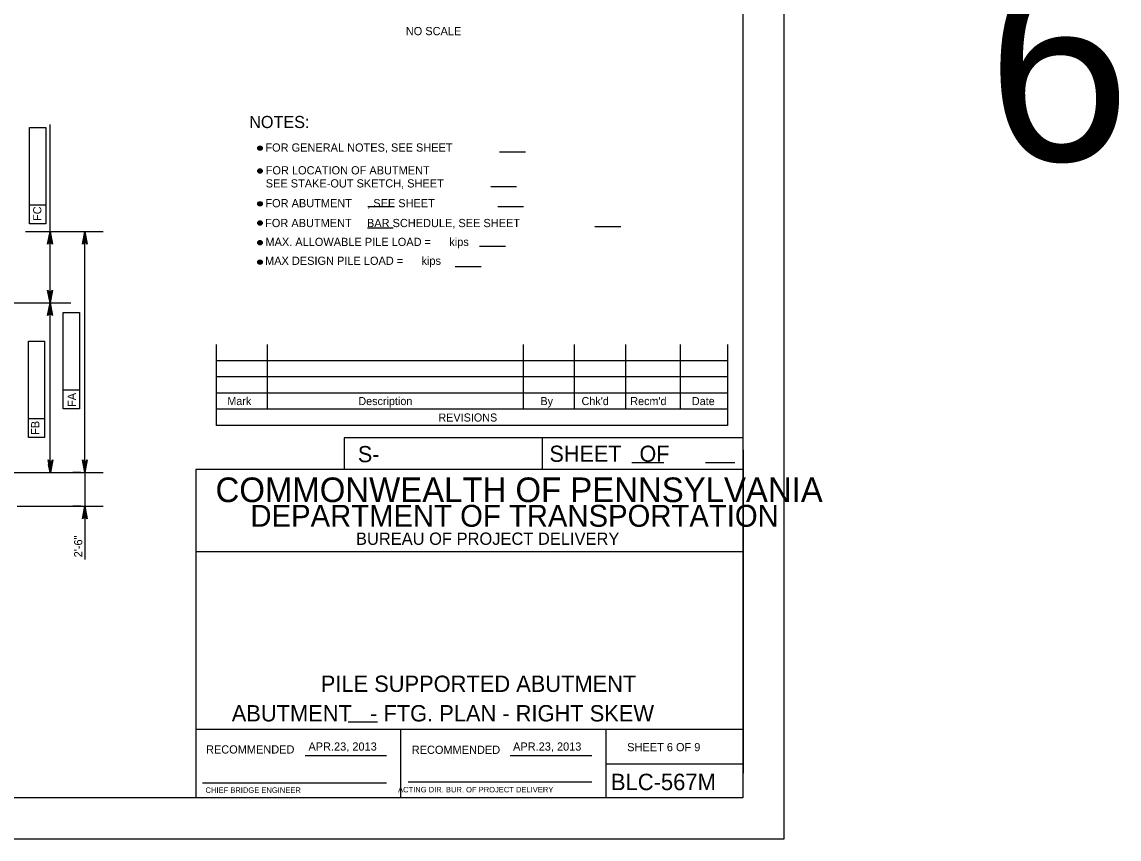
# Model space of a CAD drawing. Extents: x 638340 to 640242, y 295465 to 298435.
# Drawn here: x 639838.9 to 640240, y 297841.5 to 298140 of the extents above; entities that cross this region are included whole.
import ezdxf

# ---------------------------------------------------------------- set-up
doc = ezdxf.new("R2010")
doc.units = 0
for name, color, linetype in [('1', 7, 'Continuous'), ('2', 7, 'Continuous'), ('3', 7, 'Continuous'), ('4', 7, 'Continuous'), ('53', 7, 'Continuous'), ('Level 3', 7, 'Continuous'), ('Level 4', 7, 'Continuous'), ('PLT-BNDY', 7, 'Continuous')]:
    doc.layers.add(name, color=color, linetype=linetype)

msp = doc.modelspace()

# ---------------------------------------------------------------- linework, layer by layer
at = {"layer": '2'}
for p, q in [((640102.46, 298420.46), (640102.46, 297856.46)), ((639909.92, 298022.15), (639909.92, 297992.62)), ((639928.62, 298022.15), (639928.62, 297998.53)), ((640022.13, 298022.15), (640022.13, 297998.53)), ((640040.83, 298022.15), (640040.83, 297998.53)), ((640059.53, 298022.15), (640059.53, 297998.53)), ((640079.59, 298022.15), (640079.59, 297998.53)), ((640096.94, 298022.15), (640096.94, 297992.62)), ((640096.94, 298016.24), (639909.92, 298016.24)), ((640096.94, 298010.34), (639909.92, 298010.34)), ((640096.94, 298004.43), (639909.92, 298004.43)), ((640096.94, 297998.53), (639909.92, 297998.53)), ((640096.94, 297992.62), (639909.92, 297992.62)), ((640102.46, 297988.11), (639956.78, 297988.11)), ((639956.78, 297988.11), (639956.78, 297976.46)), ((640029.09, 297988.11), (640029.09, 297976.46)), ((640102.46, 297988.11), (640102.46, 297976.46)), ((640102.69, 297865.55), (640102.69, 297983.66)), ((640061.95, 297979), (640073.6, 297979)), ((640088.83, 297979), (640099.56, 297979)), ((640102.46, 297976.46), (639902.46, 297976.46)), ((639902.46, 297976.46), (639902.46, 297856.46)), ((640102.46, 297946.46), (639902.46, 297946.46)), ((640102.46, 297881.46), (639902.46, 297881.46)), ((639977.46, 297856.46), (639977.46, 297881.46)), ((640052.46, 297881.46), (640052.46, 297856.46)), ((639942.42, 297871.96), (639972.19, 297871.96)), ((640017.42, 297871.96), (640047.33, 297871.96)), ((640052.46, 297868.96), (640102.46, 297868.96)), ((639904.96, 297861.96), (639972.19, 297861.96)), ((639980.08, 297862.33), (640047.33, 297862.33)), ((640102.46, 297856.46), (639316.46, 297856.46))]:
    msp.add_line(p, q, dxfattribs=at)
at = {"layer": '4'}
msp.add_line((639958.24, 297884.3), (639968.9, 297884.3), dxfattribs=at)
at = {"layer": 'Level 3'}
for p, q in [((640013.58, 298092.62), (640023.03, 298092.62)), ((640010.33, 298079.91), (640019.78, 298079.91)), ((639965.42, 298072.63), (639974.86, 298072.63)), ((640012.91, 298072.62), (640022.35, 298072.62)), ((640048.43, 298065.3), (640057.88, 298065.3)), ((639965.22, 298064.83), (639974.66, 298064.83)), ((640006.25, 298058.17), (640015.7, 298058.17)), ((639997.35, 298050.73), (640006.8, 298050.73))]:
    msp.add_line(p, q, dxfattribs=at)
for centre, radius in [((639925.96, 298093.93), 0.832), ((639925.96, 298093.93), 0.624), ((639925.96, 298093.93), 0.416), ((639925.96, 298093.93), 0.208), ((639925.96, 298085.57), 0.832), ((639925.96, 298085.57), 0.624), ((639925.96, 298085.57), 0.416), ((639925.96, 298085.57), 0.208), ((639925.96, 298073.56), 0.832), ((639925.96, 298073.56), 0.624), ((639925.96, 298073.56), 0.416), ((639925.96, 298073.56), 0.208), ((639925.96, 298066.56), 0.832), ((639925.96, 298066.56), 0.624), ((639925.96, 298066.56), 0.416), ((639925.96, 298066.56), 0.208), ((639925.97, 298059.38), 0.832), ((639925.97, 298059.38), 0.624), ((639925.97, 298059.38), 0.416), ((639925.97, 298059.38), 0.208), ((639925.97, 298052.26), 0.832), ((639925.97, 298052.26), 0.624), ((639925.97, 298052.26), 0.416), ((639925.97, 298052.26), 0.208)]:
    msp.add_circle(centre, radius, dxfattribs=at)
at = {"layer": 'Level 4'}
for p, q in [((639841.74, 298066.25), (639841.74, 298101.48)), ((639841.74, 298101.48), (639847.63, 298101.48)), ((639847.63, 298101.48), (639847.63, 298066.25)), ((639849.19, 298040.31), (639849.19, 298102.62)), ((639847.63, 298073.08), (639841.74, 298073.08)), ((639847.63, 298066.25), (639841.74, 298066.25)), ((639840.22, 298063.46), (639868.68, 298063.46)), ((639846.73, 298063.46), (639853.61, 298063.46)), ((639855.63, 298063.46), (639866.37, 298063.46)), ((639861.95, 297975.36), (639861.95, 298063.46)), ((639747.78, 298037.37), (639856.83, 298037.37)), ((639843.85, 298037.37), (639853.61, 298037.37)), ((639849.19, 297978.3), (639849.19, 298034.42)), ((639854.05, 297998.64), (639854.05, 298033.88)), ((639854.05, 298033.88), (639859.94, 298033.88)), ((639859.94, 298033.88), (639859.94, 297998.64)), ((639841.28, 297988.17), (639841.28, 298023.41)), ((639841.28, 298023.41), (639847.18, 298023.41)), ((639847.18, 298023.41), (639847.18, 297988.17)), ((639859.94, 298005.48), (639854.05, 298005.48)), ((639859.94, 297998.64), (639854.05, 297998.64)), ((639847.18, 297995.01), (639841.28, 297995.01)), ((639847.18, 297988.17), (639841.28, 297988.17)), ((639747.62, 297975.36), (639868.68, 297975.36)), ((639843.85, 297975.36), (639853.61, 297975.36)), ((639855.63, 297975.36), (639866.37, 297975.36)), ((639860.48, 297975.36), (639857.53, 297975.36)), ((639861.95, 297975.36), (639861.95, 297963.08)), ((639837.24, 297963.08), (639868.68, 297963.08)), ((639860.48, 297963.08), (639857.53, 297963.08)), ((639861.95, 297960.13), (639861.95, 297943.61))]:
    msp.add_line(p, q, dxfattribs=at)
for points in [[(639849.19, 298063.46), (639850.06, 298058.81), (639849.81, 298059.17), (639849.5, 298059.35), (639849.19, 298059.41), (639848.87, 298059.35), (639848.56, 298059.17), (639848.31, 298058.81), (639849.19, 298063.46), (639848.56, 298059.17), (639848.87, 298059.35), (639849.19, 298063.46), (639849.19, 298059.41), (639849.5, 298059.35), (639849.19, 298063.46), (639849.81, 298059.17)], [(639861.95, 298063.46), (639862.82, 298058.81), (639862.57, 298059.17), (639862.26, 298059.35), (639861.95, 298059.41), (639861.63, 298059.35), (639861.32, 298059.17), (639861.07, 298058.81), (639861.95, 298063.46), (639861.32, 298059.17), (639861.63, 298059.35), (639861.95, 298063.46), (639861.95, 298059.41), (639862.26, 298059.35), (639861.95, 298063.46), (639862.57, 298059.17)], [(639849.19, 298037.37), (639848.31, 298042.02), (639848.56, 298041.66), (639848.87, 298041.48), (639849.19, 298041.42), (639849.5, 298041.48), (639849.81, 298041.66), (639850.06, 298042.02), (639849.19, 298037.37), (639849.81, 298041.66), (639849.5, 298041.48), (639849.19, 298037.37), (639849.19, 298041.42), (639848.87, 298041.48), (639849.19, 298037.37), (639848.56, 298041.66)], [(639849.19, 298037.37), (639850.06, 298032.72), (639849.81, 298033.07), (639849.5, 298033.26), (639849.19, 298033.31), (639848.87, 298033.26), (639848.56, 298033.07), (639848.31, 298032.72), (639849.19, 298037.37), (639848.56, 298033.07), (639848.87, 298033.26), (639849.19, 298037.37), (639849.19, 298033.31), (639849.5, 298033.26), (639849.19, 298037.37), (639849.81, 298033.07)], [(639849.33, 297975.36), (639848.46, 297980.01), (639848.71, 297979.65), (639849.02, 297979.46), (639849.33, 297979.41), (639849.64, 297979.46), (639849.96, 297979.65), (639850.2, 297980.01), (639849.33, 297975.36), (639849.96, 297979.65), (639849.64, 297979.46), (639849.33, 297975.36), (639849.33, 297979.41), (639849.02, 297979.46), (639849.33, 297975.36), (639848.71, 297979.65)], [(639861.95, 297975.36), (639861.07, 297980.01), (639861.32, 297979.65), (639861.63, 297979.46), (639861.95, 297979.41), (639862.26, 297979.46), (639862.57, 297979.65), (639862.82, 297980.01), (639861.95, 297975.36), (639862.57, 297979.65), (639862.26, 297979.46), (639861.95, 297975.36), (639861.95, 297979.41), (639861.63, 297979.46), (639861.95, 297975.36), (639861.32, 297979.65)], [(639861.95, 297963.08), (639862.82, 297958.43), (639862.57, 297958.78), (639862.26, 297958.97), (639861.95, 297959.02), (639861.63, 297958.97), (639861.32, 297958.78), (639861.07, 297958.43), (639861.95, 297963.08), (639861.32, 297958.78), (639861.63, 297958.97), (639861.95, 297963.08), (639861.95, 297959.02), (639862.26, 297958.97), (639861.95, 297963.08), (639862.57, 297958.78)]]:
    msp.add_lwpolyline(points, dxfattribs=at)
for points in [[(639848.69, 298060.52), (639849.68, 298060.52), (639849.19, 298063.46)], [(639861.46, 298060.52), (639862.44, 298060.52), (639861.95, 298063.46)], [(639848.69, 298040.31), (639849.68, 298040.31), (639849.19, 298037.37)], [(639848.69, 298034.42), (639849.68, 298034.42), (639849.19, 298037.37)], [(639848.69, 297978.3), (639849.68, 297978.3), (639849.19, 297975.36)], [(639861.46, 297978.3), (639862.44, 297978.3), (639861.95, 297975.36)], [(639861.46, 297960.13), (639862.44, 297960.13), (639861.95, 297963.08)]]:
    msp.add_lwpolyline(points, close=True, dxfattribs=at)
at = {"layer": 'PLT-BNDY'}
msp.add_lwpolyline([(639276.46, 298435.46), (640117.46, 298435.46), (640117.46, 297841.46), (639276.46, 297841.46)], close=True, dxfattribs=at)

# ---------------------------------------------------------------- texts
at = {"layer": '1'}
msp.add_text('SHEET 6 OF 9', height=3, dxfattribs=at).set_placement((640060.21, 297873.55))
at = {"layer": '2'}
for s, height, p in [('Mark', 2.952, (639914.02, 298000.03)), ('Description', 2.9523, (639961.92, 298000.03)), ('By', 2.952, (640028.49, 298000.03)), ("Chk'd", 2.952, (640043.52, 298000.03)), ("Recm'd", 2.953, (640061.33, 298000.03)), ('Date', 2.952, (640083.86, 298000.03)), ('REVISIONS', 2.952, (639991.2, 297994.01)), ('S-', 5.905, (639961.73, 297979.17)), ('SHEET   OF', 5.907, (640031.78, 297979.31)), ('COMMONWEALTH OF PENNSYLVANIA', 9, (639909.71, 297964.58)), ('DEPARTMENT OF TRANSPORTATION', 8.0002, (639922.46, 297955.58)), ('BUREAU OF PROJECT DELIVERY', 4.5, (639961.05, 297948.96)), ('APR.23, 2013', 3, (639943.67, 297873.77)), ('APR.23, 2013', 3, (640018.48, 297873.77)), ('BLC-567M', 6, (640054.27, 297859.33)), ('  ACTING DIR. BUR. OF PROJECT DELIVERY', 2.0002, (639974.9, 297858.51)), ('CHIEF BRIDGE ENGINEER', 2.0002, (639906.05, 297858.33))]:
    msp.add_text(s, height=height, dxfattribs=at).set_placement(p)
for p in [(639906.23, 297872.71), (639981.44, 297872.58)]:
    msp.add_text('RECOMMENDED', height=3, rotation=360, dxfattribs=at).set_placement(p)
at = {"layer": '3'}
msp.add_text('NOTES:', height=4.429, dxfattribs=at).set_placement((639922.01, 298101.28))
at = {"layer": '4'}
for s, height, p in [('NO SCALE', 3, (639979.26, 298135.21)), ('PILE SUPPORTED ABUTMENT', 5.9716, (639948.18, 297895.21)), ('ABUTMENT   - FTG. PLAN - RIGHT SKEW', 5.9716, (639915.63, 297884.43))]:
    msp.add_text(s, height=height, dxfattribs=at).set_placement(p)
at = {"layer": '53'}
msp.add_text('6', height=70.32, dxfattribs=at).set_placement((640191.88, 298089.34))
at = {"layer": 'Level 3'}
for s, p in [('FOR GENERAL NOTES, SEE SHEET    ', (639927.93, 298092.66)), ('FOR LOCATION OF ABUTMENT', (639928.06, 298084.33)), ('SEE STAKE-OUT SKETCH, SHEET    ', (639928.06, 298079.56)), ('FOR ABUTMENT     , SEE SHEET', (639927.93, 298072.33)), ('FOR ABUTMENT     BAR SCHEDULE, SEE SHEET    ', (639927.85, 298065.07)), ('MAX. ALLOWABLE PILE LOAD =      kips', (639927.95, 298058.17)), ('MAX DESIGN PILE LOAD =      kips', (639927.82, 298051.28))]:
    msp.add_text(s, height=3.0001, dxfattribs=at).set_placement(p)
at = {"layer": 'Level 4'}
for s, p in [('FC', (639846.04, 298067.31)), ('FA', (639858.66, 297999.36)), ('FB', (639845.29, 297989.15)), ('2\'-6"', (639861.01, 297944.39))]:
    msp.add_text(s, height=3, rotation=90, dxfattribs=at).set_placement(p)

doc.saveas('drawing.dxf')
